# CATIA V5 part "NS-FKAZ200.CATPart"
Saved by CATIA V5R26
Part number: NS-FKAZ200
Bounding box of the stored display mesh (mm): x -120.601 to 120.601, y -249.867 to 0, z -57.2 to 55.6
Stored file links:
  R:\Document\坂尻\その他\ナベヤデータ変換\安全カバーキャスター\MCBKSAZ200\NS-FKAZ200.CATPart
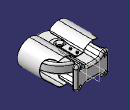
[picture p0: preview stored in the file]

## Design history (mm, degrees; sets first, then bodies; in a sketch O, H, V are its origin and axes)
Body1 (main body)
  Solid1: solid without history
